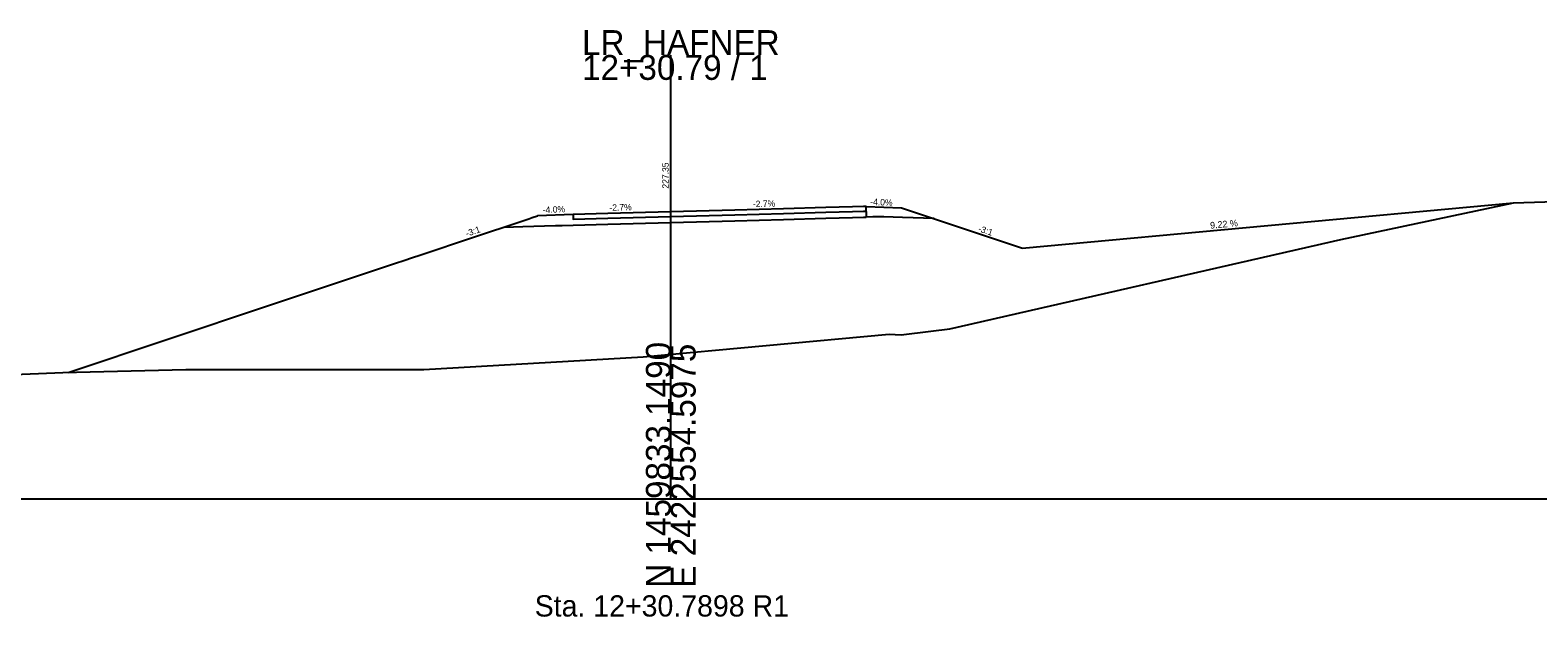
# Model space of a CAD drawing. Extents: x -26 to 403, y -13 to 3053.
# Drawn here: x 127.8 to 297.7, y 2486.7 to 2552.8 of the extents above; entities that cross this region are included whole.
import ezdxf

# ---------------------------------------------------------------- set-up
doc = ezdxf.new("R2010")
doc.units = 0
for name, color, linetype in [('CONST_DCH', 7, 'Continuous'), ('Default', 7, 'Continuous'), ('Draft_XS_Text', 7, 'Continuous'), ('DTM_CORRIDOR', 7, 'Continuous'), ('DTM_TEMP_DROP', 7, 'Continuous'), ('DTM_X_GROUND', 7, 'Continuous'), ('XS_CELL', 7, 'Continuous'), ('XS_P_ASPHALT', 7, 'Continuous'), ('XS_P_GROUND', 7, 'Continuous'), ('XS_P_SHOULDER', 7, 'Continuous'), ('XS_P_SUBGRADE_GRANULAR', 7, 'Continuous'), ('XS_P_TX_CLEARZONE', 7, 'Continuous'), ('XS_P_TX_FS_BS', 7, 'Continuous')]:
    doc.layers.add(name, color=color, linetype=linetype)

msp = doc.modelspace()

# ---------------------------------------------------------------- linework, layer by layer
at = {"layer": 'Default'}
msp.add_line((222, 2532.39), (222, 2531.72), dxfattribs=at)
at = {"layer": 'DTM_X_GROUND'}
msp.add_lwpolyline([(109.45, 2513.33), (131.53, 2514.24), (145.37, 2514.58), (172.2, 2514.57), (196.87, 2516.02), (224.6, 2518.56), (225.93, 2518.49), (229.29, 2518.88), (231.43, 2519.16), (275.47, 2529.21), (294.91, 2533.34), (298.45, 2533.45), (304.45, 2533.67), (306.49, 2533.73), (313.87, 2534), (326.53, 2534.53), (341.29, 2534.88), (352.35, 2535.04), (356.21, 2535.32), (360.71, 2535.67), (376.02, 2537.6), (388.64, 2539.12), (400, 2539.97)], dxfattribs=at)
at = {"layer": 'XS_CELL'}
for p, q in [((200, 2500), (200, 2550)), ((0, 2500), (200, 2500)), ((200, 2500), (400, 2500))]:
    msp.add_line(p, q, dxfattribs=at)
at = {"layer": 'XS_P_ASPHALT'}
msp.add_lwpolyline([(192.9, 2532.15), (189, 2532.04), (189, 2531.71), (189, 2531.5), (192.9, 2531.61), (200, 2531.8), (207.2, 2532), (212.71, 2532.15), (217.45, 2532.28), (220.47, 2532.36), (221.71, 2532.4), (222, 2532.41), (222, 2532.61), (222, 2532.95), (221.71, 2532.94), (220.47, 2532.91), (217.45, 2532.82), (212.71, 2532.69), (207.2, 2532.54), (200, 2532.35), (192.9, 2532.15)], dxfattribs=at)
at = {"layer": 'XS_P_GROUND'}
msp.add_line((239.58, 2528.24), (294.91, 2533.34), dxfattribs=at)
for points in [[(226, 2532.79), (227, 2532.45), (239.62, 2528.25)], [(132.13, 2514.25), (154.56, 2521.74), (169.1, 2526.59), (169.82, 2526.82), (171.01, 2527.22), (171.63, 2527.43), (172.65, 2527.77), (176.87, 2529.17), (184, 2531.55), (184.38, 2531.68), (185, 2531.88)]]:
    msp.add_lwpolyline(points, dxfattribs=at)
at = {"layer": 'XS_P_SHOULDER'}
for points in [[(189, 2532.04), (185, 2531.88)], [(222, 2532.95), (226, 2532.79)]]:
    msp.add_lwpolyline(points, dxfattribs=at)
at = {"layer": 'XS_P_SUBGRADE_GRANULAR'}
for points in [[(181.22, 2530.62), (183.33, 2530.68), (187, 2530.78), (187.75, 2530.8), (189, 2530.84)], [(189, 2530.84), (192.9, 2530.94), (200, 2531.14)], [(200, 2531.14), (207.2, 2531.33), (212.71, 2531.49), (217.45, 2531.61), (220.47, 2531.7), (221.71, 2531.73), (222, 2531.74)], [(229.66, 2531.57), (226.1, 2531.71), (224, 2531.79), (222.75, 2531.76), (222, 2531.74)]]:
    msp.add_lwpolyline(points, dxfattribs=at)

# ---------------------------------------------------------------- texts
at = {"layer": 'CONST_DCH'}
for p in [(188.99, 2532.04), (199.99, 2532.34), (221.99, 2532.94)]:
    msp.add_text('X', height=0.012, dxfattribs=at).set_placement(p)
at = {"layer": 'Draft_XS_Text'}
msp.add_text('Sta. 12+30.7898 R1', height=2.4, dxfattribs=at).set_placement((184.67, 2486.75))
at = {"layer": 'DTM_CORRIDOR'}
for p in [(226.99, 2532.45), (183.99, 2531.54), (171, 2527.19), (171, 2527.19)]:
    msp.add_text('X', height=0.012, dxfattribs=at).set_placement(p)
at = {"layer": 'DTM_TEMP_DROP'}
for p in [(225.99, 2532.78), (184.99, 2531.88)]:
    msp.add_text('X', height=0.012, dxfattribs=at).set_placement(p)
at = {"layer": 'XS_CELL'}
for s, p in [('LR_HAFNER', (190, 2550)), ('12+30.79 / 1', (190, 2547.2))]:
    msp.add_text(s, height=2.8, dxfattribs=at).set_placement(p)
for s, p in [('N 1459833.1490', (200, 2490)), ('E 2422554.5975', (202.8, 2490))]:
    msp.add_text(s, height=2.8, rotation=90, dxfattribs=at).set_placement(p)
at = {"layer": 'XS_P_ASPHALT'}
msp.add_text('X', height=0.012, dxfattribs=at).set_placement((148.52, 2519.7))
at = {"layer": 'XS_P_GROUND'}
msp.add_text('X', height=0.012, dxfattribs=at).set_placement((148.52, 2519.7))
at = {"layer": 'XS_P_TX_CLEARZONE'}
msp.add_text('227.35   ', height=0.72, rotation=90, dxfattribs=at).set_placement((199.76, 2534.95))
at = {"layer": 'XS_P_TX_FS_BS'}
for s, height, rotation, p in [('-4.0%', 0.72, 357.7096, (222.45, 2533.11)), ('-4.0%', 0.72, 2.2906, (185.59, 2532.19)), ('-2.7%', 0.72, 1.5674, (193.09, 2532.44)), ('-2.7%', 0.72, 1.5674, (209.25, 2532.86)), ('-3:1', 0.72, 18.4349, (177.04, 2529.53)), ('-3:1', 0.72, 341.5653, (234.56, 2530.15)), ('9.22 %', 0.75, 5.2683, (260.78, 2530.43))]:
    msp.add_text(s, height=height, rotation=rotation, dxfattribs=at).set_placement(p)

doc.saveas('drawing.dxf')
